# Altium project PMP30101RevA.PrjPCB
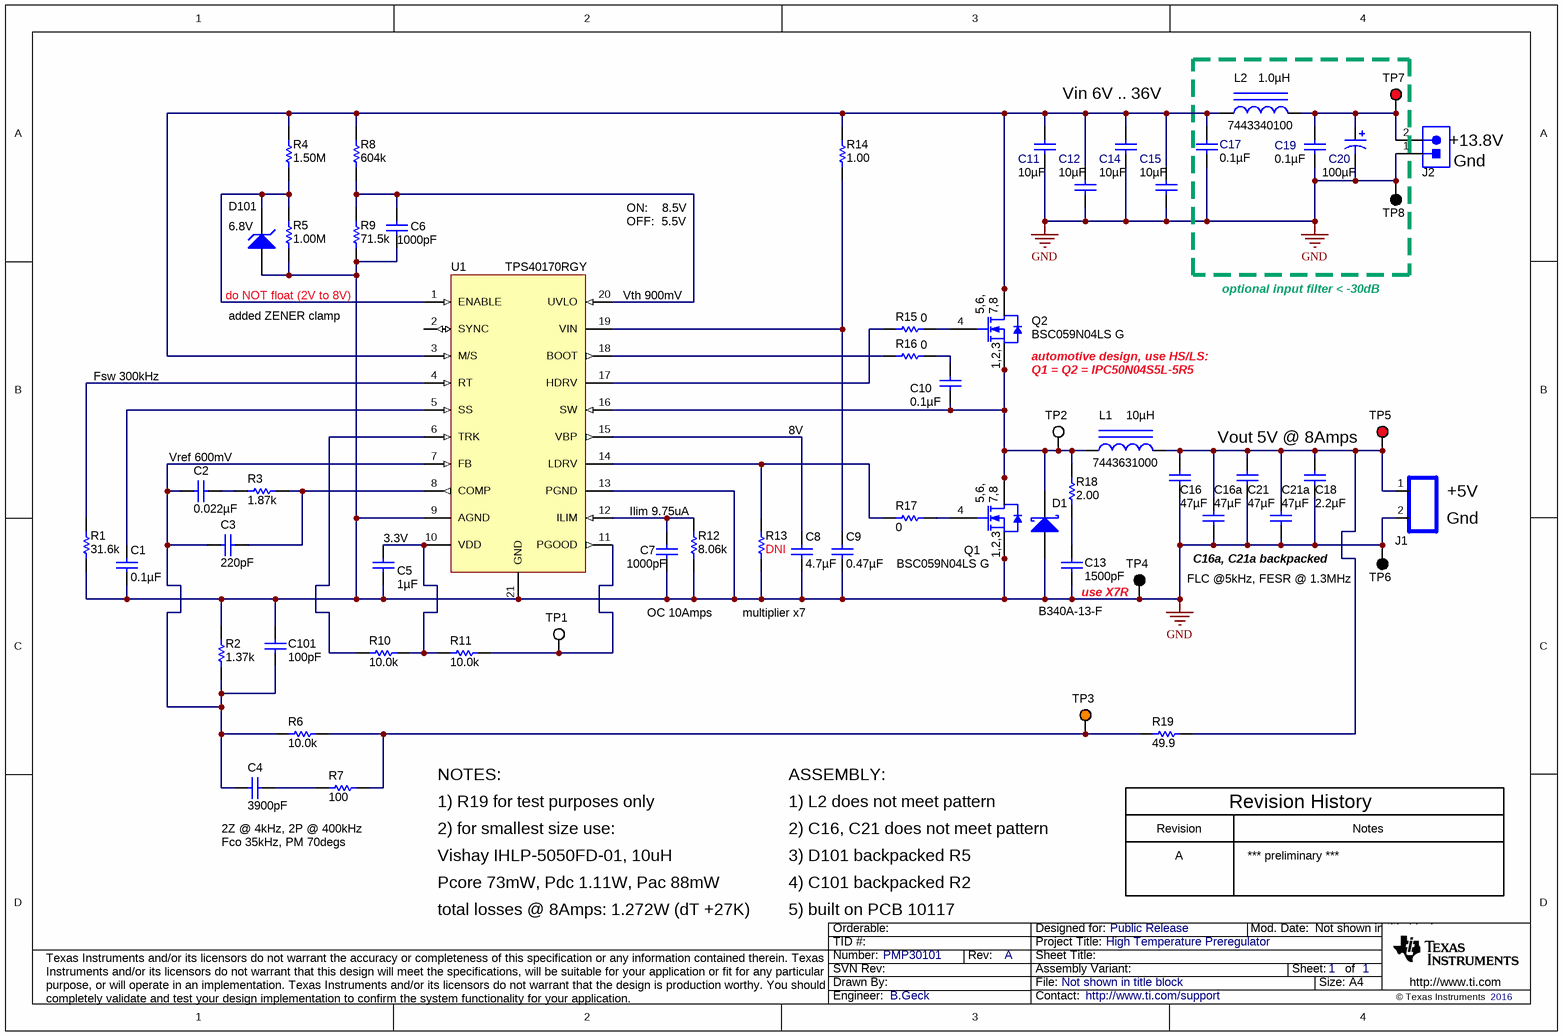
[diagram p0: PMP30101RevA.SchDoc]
CopyrightYear: 2016; PCB_Layout: B.Geck; PCB_Rev: A; PRJ_Customer: Public Release; PRJ_Engineer: B.Geck; PRJ_Number: PMP30101; PRJ_Title: High Temperature Preregulator; SCH_Rev: A; TechSupport: http://www.ti.com/support
1 sheet, 60 parts. Net scope: global (net labels, ports and power ports of the same name join across sheets).

## Sheet PMP30101RevA.SchDoc
size A4; Date: Not shown in title block; ApprovedBy: Not shown in title block; CheckedBy: Not shown in title block; Author: Not shown in title block; CompanyName: Not shown in title block; Engineer: Not shown in title block; Organization: Not shown in title block; Address1: Not shown in title block; Address2: Not shown in title block; Address3: Not shown in title block; Address4: Not shown in title block; DocumentNumber: 1; Revision: Use project parameter SCH_Rev; SheetNumber: 1; SheetTotal: 1; PageSetup: Record=PageOptions¦CenterHorizontal=True¦CenterVertical=True¦PrintScale=0.70¦XCorrection=1.00¦YCorrection=1.00¦PrintKind=0¦BorderSize=5000000¦LeftOffset=0¦BottomOffset=0¦Orientation=2¦PaperLength=1000¦PaperWidth=1000¦Scale=100¦PaperSource=15¦PrintQuality=600¦MediaType=1¦DitherType=10¦PaperKind=A4¦PrintScaleMode=1

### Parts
C1  ValueDisplayed: 0.1µF  [0402]  (hidden comment: GRM155R71C104KA88D)
C2  ValueDisplayed: 0.022µF  [0402]  (hidden comment: GRM155R71E223KA61D)
C3  ValueDisplayed: 220pF  [0402]  (hidden comment: GRM155R71H221KA01D)
C4  ValueDisplayed: 3900pF  [0402]  (hidden comment: GRM155R71H392KA01D)
C5  ValueDisplayed: 1µF  [0603]  (hidden comment: GRM188R71C105KA12D)
C6  ValueDisplayed: 1000pF  [0402]  (hidden comment: GRM155R71C102KA01D)
C7  ValueDisplayed: 1000pF  [0402]  (hidden comment: GRM155R71C102KA01D)
C8  ValueDisplayed: 4.7µF  [0805_HV]  (hidden comment: GRM21BR71C475KA73L)
C9  ValueDisplayed: 0.47µF  [0805_HV]  (hidden comment: GRM21BR72A474KA73L)
C10  ValueDisplayed: 0.1µF  [0603]  (hidden comment: GRM188R72A104KA35D)
C11  ValueDisplayed: 10µF  [1210_270]  (hidden comment: GRM32ER71H106KA12L)
C12  ValueDisplayed: 10µF  [1210_270]  (hidden comment: GRM32ER71H106KA12L)
C13  ValueDisplayed: 1500pF  [0603]  (hidden comment: GRM188R72A152KA01D)
C14  ValueDisplayed: 10µF  [1210_270]  (hidden comment: GRM32ER71H106KA12L)
C15  ValueDisplayed: 10µF  [1210_270]  (hidden comment: GRM32ER71H106KA12L)
C16  ValueDisplayed: 47µF  [1210_270]  (hidden comment: GRM32ER71A476KE15L)
C16a  ValueDisplayed: 47µF  [1210_270]  (hidden comment: GRM32ER71A476KE15L)
C17  ValueDisplayed: 0.1µF  [0603]  (hidden comment: GRM188R71H104KA93D)
C18  ValueDisplayed: 2.2µF  [0603]  (hidden comment: GRM188R71A225KE15D)
C19  ValueDisplayed: 0.1µF  [0603]  (hidden comment: GRM188R71H104KA93D)
C20  ValueDisplayed: 100µF  [SM_RADIAL_10BMM]  (hidden comment: EEHZC1H101P)
C21  ValueDisplayed: 47µF  [1210_270]  (hidden comment: GRM32ER71A476KE15L)
C21a  ValueDisplayed: 47µF  [1210_270]  (hidden comment: GRM32ER71A476KE15L)
C101  ValueDisplayed: 100pF  [0402]  (hidden comment: GRM1555C1H101JA01D)
D1  B340A-13-F  [SMA]
D101  value 6.8V  [SOD-323]  (hidden comment: MMSZ5235BS-7-F)
J1  TBLK_15A_2X5.1MM  [TB_2X5.1MM]  (value not drawn)
J2  ED555/2DS  [TERM_BLK_ED555-2DS]  (value not drawn)
L1  7443631000  ValueDisplayed: 10µH  [WE-HCF_2013]
L2  7443340100  ValueDisplayed: 1.0µH  [WE-HCC-8X7]
Q1  BSC059N04LS G  [PG-TDSON-8]
Q2  BSC059N04LS G  [PG-TDSON-8]
R1  ValueDisplayed: 31.6k  [0402]  (hidden comment: CRCW040231K6FKED)
R2  ValueDisplayed: 1.37k  [0402]  (hidden comment: CRCW04021K37FKED)
R3  ValueDisplayed: 1.87k  [0402]  (hidden comment: CRCW04021K87FKED)
R4  ValueDisplayed: 1.50M  [0603]  (hidden comment: CRCW06031M50FKEA)
R5  ValueDisplayed: 1.00M  [0402]  (hidden comment: CRCW04021M00FKED)
R6  ValueDisplayed: 10.0k  [0402]  (hidden comment: CRCW040210K0FKED)
R7  ValueDisplayed: 100  [0402]  (hidden comment: CRCW0402100RFKED)
R8  ValueDisplayed: 604k  [0603]  (hidden comment: CRCW0603604KFKEA)
R9  ValueDisplayed: 71.5k  [0402]  (hidden comment: CRCW040271K5FKED)
R10  ValueDisplayed: 10.0k  [0402]  (hidden comment: CRCW040210K0FKED)
R11  ValueDisplayed: 10.0k  [0402]  (hidden comment: CRCW040210K0FKED)
R12  ValueDisplayed: 8.06k  [0402]  (hidden comment: CRCW04028K06FKED)
R13  ValueDisplayed: DNI  [0402]  (hidden comment: CRCW040210K0FKED)
R14  ValueDisplayed: 1.00  [0603]  (hidden comment: CRCW06031R00FKEA)
R15  ValueDisplayed: 0  [0402]  (hidden comment: CRCW04020000Z0ED)
R16  ValueDisplayed: 0  [0402]  (hidden comment: CRCW04020000Z0ED)
R17  ValueDisplayed: 0  [0402]  (hidden comment: CRCW04020000Z0ED)
R18  ValueDisplayed: 2.00  [1210M]  (hidden comment: ERJ-14BQF2R0U)
R19  ValueDisplayed: 49.9  [0402]  (hidden comment: CRCW040249R9FKED)
TP1  5002  [Keystone5002]  (value not drawn)
TP2  5002  [Keystone5002]  (value not drawn)
TP3  5003  [Keystone5003]  (value not drawn)
TP4  5001  [Keystone5001]  (value not drawn)
TP5  5000  [Keystone5000]  (value not drawn)
TP6  5001  [Keystone5001]  (value not drawn)
TP7  5000  [Keystone5000]  (value not drawn)
TP8  5001  [Keystone5001]  (value not drawn)
U1  TPS40170RGY  [RGY0020A]

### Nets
GND: C1.2 C5.2 C6.2 C7.2 C8.2 C9.2 C11.2 C12.2 C13.2 C14.2 C15.2 C16.2 C16a.2 C17.2 C18.2 C19.2 C20.2(-) C21.2 C21a.2 C101.1 D1.2(A) D101.2(A) J1.2 J2.1 Q1.1(S) Q1.2(S) Q1.3(S) R1.1 R2.2 R5.1 R9.1 R12.1 R13.1 TP4.1 TP6.1 TP8.1 U1.9(AGND) U1.13(PGND) U1.21(GND)
NetC1_1: C1.1 U1.5(SS)
NetC2_1: C2.1 R3.1
NetC2_2: C2.2 C3.2 C4.2 C101.2 R2.1 R6.2 U1.7(FB)
NetC3_1: C3.1 R3.2 U1.8(COMP)
NetC4_1: C4.1 R7.1
NetC5_1: C5.1 R10.1 R11.2 U1.10(VDD)
NetC6_1: C6.1 R8.1 R9.2 U1.20(UVLO)
NetC7_1: C7.1 R12.2 U1.12(ILIM)
NetC8_1: C8.1 U1.15(VBP)
NetC9_1: C9.1 R14.1 U1.19(VIN)
NetC10_1: C10.1 R16.2
NetC10_2: C10.2 D1.1(K) L1.1 Q1.5(D) Q1.6(D) Q1.7(D) Q1.8(D) Q1.9(D) Q2.1(S) Q2.2(S) Q2.3(S) R18.2 TP2.1 U1.16(SW)
NetC11_1: C11.1 C12.1 C14.1 C15.1 C17.1 L2.1 Q2.5(D) Q2.6(D) Q2.7(D) Q2.8(D) Q2.9(D) R4.2 R8.2 R14.2 U1.3(M/S)
NetC13_1: C13.1 R18.1
NetC16_1: C16.1 C16a.1 C18.1 C21.1 C21a.1 J1.1 L1.2 R19.2 TP5.1
NetC19_1: C19.1 C20.1(+) J2.2 L2.2 TP7.1
NetD101_1: D101.1(K) R4.1 R5.2 U1.1(ENABLE)
NetQ1_4: Q1.4(G) R17.2
NetQ2_4: Q2.4(G) R15.2
NetR1_2: R1.2 U1.4(RT)
NetR6_1: R6.1 R7.2 R19.1 TP3.1
NetR10_2: R10.2 U1.6(TRK)
NetR11_1: R11.1 TP1.1 U1.11(PGOOD)
NetR13_2: R13.2 R17.1 U1.14(LDRV)
NetR15_1: R15.1 U1.17(HDRV)
NetR16_1: R16.1 U1.18(BOOT)

Not connected (* = marked no-connect by the designer): U1 2(SYNC)

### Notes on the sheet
- Vin 6V .. 36V
- (near J2) Gnd
- (near J2) +13.8V
- ON:    8.5V
- OFF:  5.5V
- added ZENER clamp
- do NOT float (2V to 8V)
- (near U1) Vth 900mV
- optional input filter < -30dB
- Fsw 300kHz
- (near Q2) automotive design, use HS/LS:
- (near Q2) Q1 = Q2 = IPC50N04S5L-5R5
- 8V
- Vout 5V @ 8Amps
- Vref 600mV
- (near R12) Ilim 9.75uA
- (near J1) +5V
- (near J1) Gnd
- (near C5) 3.3V
- FLC @5kHz, FESR @ 1.3MHz
- C16a, C21a backpacked
- OC 10Amps
- multiplier x7
- use X7R
- NOTES:
- ASSEMBLY:
- 2Z @ 4kHz, 2P @ 400kHz
- Fco 35kHz, PM 70degs
- 1) R19 for test purposes only
- 2) for smallest size use:
- Vishay IHLP-5050FD-01, 10uH
- 1) L2 does not meet pattern
- 2) C16, C21 does not meet pattern
- 3) D101 backpacked R5
- Revision
- A
- *** preliminary ***
- Revision History
- Notes
- Pcore 73mW, Pdc 1.11W, Pac 88mW
- total losses @ 8Amps: 1.272W (dT +27K)
- 5) built on PCB 10117
- 4) C101 backpacked R2

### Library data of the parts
C1 = GRM155R71C104KA88D: CAP, CERM, 0.1 µF, 16 V, +/- 10%, X7R, 0402; Manufacturer: MuRata; Polarized: N; CompType: Capacitor; Value: 0.1uF; U/M: EA; Cap_F: 0.0000001; Tolerance_%: 10; Value1: Unknown; VDC_V: 16; Value2: 16V; TaMin_C: -55; TaMax_C: 125
C2 = GRM155R71E223KA61D: CAP, CERM, 0.022 µF, 25 V, +/- 10%, X7R, 0402; Manufacturer: MuRata; Polarized: N; CompType: Capacitor; Value: 0.022uF; U/M: EA; Cap_F: 0.000000022; Tolerance_%: 10; Value1: Unknown; VDC_V: 25; Value2: 25V; TaMin_C: -55; TaMax_C: 125; SizeArea_mm2: 0.5; SizeAreaWB_mm2: 3; SizeX_mm: 1; SizeZ_mm: 0.6; AEC Category: Q200
C3 = GRM155R71H221KA01D: CAP, CERM, 220 pF, 50 V, +/- 10%, X7R, 0402; Manufacturer: MuRata; Polarized: N; CompType: Capacitor; Value: 220pF; U/M: EA; Cap_F: 0.00000000022; Tolerance_%: 10; Value1: Unknown; VDC_V: 50; Value2: 50V; TaMin_C: -55; TaMax_C: 125; SizeArea_mm2: 0.5; SizeAreaWB_mm2: 3; SizeX_mm: 1; SizeZ_mm: 0.6; AEC Category: Q200
C4 = GRM155R71H392KA01D: CAP, CERM, 3900 pF, 50 V, +/- 10%, X7R, 0402; Manufacturer: MuRata; Polarized: N; CompType: Capacitor; Value: 3900pF; U/M: EA; Cap_F: 0.0000000039; Tolerance_%: 10; Value1: Unknown; VDC_V: 50; Value2: 50V; TaMin_C: -55; TaMax_C: 125; SizeArea_mm2: 0.5; SizeAreaWB_mm2: 3; SizeX_mm: 1; SizeZ_mm: 0.6; AEC Category: Q200
C5 = GRM188R71C105KA12D: CAP, CERM, 1 µF, 16 V, +/- 10%, X7R, 0603; Manufacturer: MuRata; Polarized: N; CompType: Capacitor; Value: 1uF; U/M: EA; Cap_F: 0.000001; Tolerance_%: 10; ESR_ohm: 0.011; Value1: 0.011 ohm; VDC_V: 16; Value2: 16V; TaMin_C: -55; TaMax_C: 125
C6 C7 = GRM155R71C102KA01D: CAP, CERM, 1000 pF, 16 V, +/- 10%, X7R, 0402; Manufacturer: MuRata; Polarized: N; CompType: Capacitor; Value: 1000pF; U/M: EA; Cap_F: 0.000000001; Tolerance_%: 10; Value1: Unknown; VDC_V: 16; Value2: 16V; TaMin_C: -55; TaMax_C: 125
C8 = GRM21BR71C475KA73L: CAP, CERM, 4.7 µF, 16 V, +/- 10%, X7R, 0805; Manufacturer: MuRata; Polarized: N; CompType: Capacitor; Value: 4.7uF; U/M: EA; Cap_F: 0.0000047; Tolerance_%: 10; ESR_ohm: 0.006; Value1: 0.006 ohm; VDC_V: 16; Value2: 16V; TaMin_C: -55; TaMax_C: 125; Cap_Case: 0805
C9 = GRM21BR72A474KA73L: CAP, CERM, 0.47 µF, 100 V, +/- 10%, X7R, 0805; Manufacturer: MuRata; Polarized: N; CompType: Capacitor; Value: 0.47uF; U/M: EA; Cap_F: 0.00000047; Tolerance_%: 10; Value1: Unknown; VDC_V: 100; Value2: 100V; TaMin_C: -55; TaMax_C: 125; Cap_Case: 0805
C10 = GRM188R72A104KA35D: CAP, CERM, 0.1 µF, 100 V, +/- 10%, X7R, 0603; Manufacturer: MuRata; Polarized: N; CompType: Capacitor; Value: 0.1uF; U/M: EA; Cap_F: 0.0000001; Tolerance_%: 10; Value1: Unknown; VDC_V: 100; Value2: 100V; TaMin_C: -55; TaMax_C: 125
C11 C12 C14 C15 = GRM32ER71H106KA12L: CAP, CERM, 10 µF, 50 V, +/- 10%, X7R, 1210; Manufacturer: MuRata; Polarized: N; CompType: Capacitor; Value: 10uF; U/M: EA; Cap_F: 0.00001; Tolerance_%: 10; Value1: Unknown; VDC_V: 50; Value2: 50V; TaMin_C: -55; TaMax_C: 125; Cap_Case: 1210; SizeArea_mm2: 8; SizeAreaWB_mm2: 14.7; SizeX_mm: 3.2; SizeY_mm: 2.5; SizeZ_mm: 2.7; AEC Category: Q200
C13 = GRM188R72A152KA01D: CAP, CERM, 1500 pF, 100 V, +/- 10%, X7R, 0603; Manufacturer: MuRata; Polarized: N; CompType: Capacitor; Value: 1500pF; U/M: EA; Cap_F: 0.0000000015; Tolerance_%: 10; Value1: Unknown; VDC_V: 100; Value2: 100V; TaMin_C: -55; TaMax_C: 125; SizeArea_mm2: 1.28; SizeAreaWB_mm2: 4.68; SizeX_mm: 1.6; SizeY_mm: 0.8; SizeZ_mm: 1; AEC Category: Q200
C16 C16a C21 C21a = GRM32ER71A476KE15L: CAP, CERM, 47 µF, 10 V, +/- 10%, X7R, 1210; Manufacturer: MuRata; Polarized: N; CompType: Capacitor; Value: 47uF; U/M: EA; Cap_F: 0.000047; Tolerance_%: 10; Value1: Unknown; Value2: 10V; TaMin_C: -55; TaMax_C: 125; Cap_Case: 1210; SizeArea_mm2: 8; SizeAreaWB_mm2: 14.7; SizeX_mm: 3.2; SizeY_mm: 2.5; SizeZ_mm: 2.7; AEC Category: Q200
C17 C19 = GRM188R71H104KA93D: CAP, CERM, 0.1 µF, 50 V, +/- 10%, X7R, 0603; Manufacturer: MuRata; Polarized: N; CompType: Capacitor; Value: 0.1uF; U/M: EA; Cap_F: 0.0000001; Tolerance_%: 10; Value1: Unknown; VDC_V: 50; Value2: 50V; TaMin_C: -55; TaMax_C: 125; SizeArea_mm2: 1.28; SizeAreaWB_mm2: 4.68; SizeX_mm: 1.6; SizeY_mm: 0.8; SizeZ_mm: 1; AEC Category: Q200
C18 = GRM188R71A225KE15D: CAP, CERM, 2.2 µF, 10 V, +/- 10%, X7R, 0603; Manufacturer: MuRata; Polarized: N; CompType: Capacitor; Value: 2.2uF; U/M: EA; Cap_F: 0.0000022; Tolerance_%: 10; ESR_ohm: 0.009; Value1: 0.009 ohm; Value2: 10V; TaMin_C: -55; TaMax_C: 125
C20 = EEHZC1H101P: CAP, Polymer Hybrid, 100 µF, 50 V, +/- 20%, 28 ohm, 10x10 SMD; Manufacturer: Panasonic; Polarized: Y; CompType: Capacitor; Value: 100uF; U/M: EA; Cap_F: 0.0001; Tolerance_%: 20; Value1: 28 ohm; VDC_V: 50; Value2: 50V; ESR_ohm: 28; IRMS_A: 1.6; TaMin_C: -55; TaMax_C: 125; AEC Category: Q200
C101 = GRM1555C1H101JA01D: CAP, CERM, 100 pF, 50 V, +/- 5%, C0G/NP0, 0402; Manufacturer: MuRata; Polarized: N; CompType: Capacitor; Value: 100pF; U/M: EA; Cap_F: 0.0000000001; Tolerance_%: 5; Value1: Unknown; VDC_V: 50; Value2: 50V; TaMin_C: -55; TaMax_C: 125; SizeArea_mm2: 0.5; SizeAreaWB_mm2: 3; SizeX_mm: 1; SizeZ_mm: 0.6; AEC Category: Q200
D1 = B340A-13-F: Diode, Schottky, 40 V, 3 A, SMA; Manufacturer: Diodes Inc.; U/M: EA; Vf_V: 0.5; Value: 40V; Value1: 3A; Value2: 0.5V; Io_A: 3; Vr_V: 40; TJmax_C: 125; RJC_CperW: 25; SizeAreaWB_mm2: 37.3428; SizeArea_mm2: 16.3228; SizeX_mm: 5.59; SizeY_mm: 2.92; SizeZ_mm: 2.87; AEC Category: Q101
D101 = MMSZ5235BS-7-F: Diode, Zener, 6.8 V, 200 mW, SOD-323; Manufacturer: Diodes Inc.; SymbolCreator: a0412235; U/M: EA; Power_W: 0.2; Vz_V: 6.8; Value1: 0.2W; RJA_CperW: 350; SizeAreaWB_mm2: 8.695; SizeArea_mm2: 3.645; SizeX_mm: 2.7; SizeY_mm: 1.35; SizeZ_mm: 1; AEC Category: Q101
J1 = TBLK_15A_2X5.1MM: Terminal Block, 2-pin, 15-A, 5.1mm; Manufacturer: OST; PartNumber: ED120/2DS; area: 141600; Value: ED120/2DS
J2 = ED555/2DS: Terminal Block, 6A, 3.5mm Pitch, 2-Pos, TH; Manufacturer: On-Shore Technology; SymbolCreator: a0412235; CompType: Connector; U/M: EA
L1 = 7443631000: Inductor, Shielded Drum Core, Mn-Zn, 10 µH, 16 A, 0.00796 ohm, SMD; Manufacturer: Wurth Elektronik; Value: 10uH; Ind_H: 10.0E-6; Imax_A: 16; Irms: 16A @ 50C rise; Isat: 23A @ 30% inductance drop; Value2: 16A; AEC Category: Q200
L2 = 7443340150: Inductor, Shielded Drum Core, Ferrite, 1.0 µH, 17 A, 0.0036 ohm, SMD; Manufacturer: Wurth Elektronik eiSos; Value: 1.0uH; Ind_H: 1.0E-6; Imax_A: 17; Irms: 17A @ 50C rise; Isat: 24A @ 30% inductance drop; DCR_ohm: 0.0036; Value2: 17A
Q1 Q2 = BSC059N04LS G: MOSFET, N-CH, 40 V, 73 A, PG-TDSON-8; Manufacturer: Infineon Technologies; Alternate Manufacturer: None; U/M: EA; ChType: N; Value: 40V; VdsMax_V: 40; Value1: 0.0085 ohm; Rdson45_ohm: 0.0085; Value2: 30 nC; QgTyp_nC: 30; Vgs_V: 20; IdsMax_A: 73; SizeAreaWB_mm2: 55.131; SizeArea_mm2: 29.351; SizeX_mm: 5.99; SizeY_mm: 4.9; SizeZ_mm: 1.12; AEC Category: Q101
R1 = CRCW040231K6FKED: RES, 31.6 k, 1%, 0.063 W, 0402; Manufacturer: Vishay-Dale; CompType: Resistor; Value: 31.6k; Res_ohm: 31600; Value_Code: 31k6; Tolerance_%: 1; Power_W: 0.063; Value2: 0.063W; VDC_V: 50; TempCo: 100 ppm/C; SizeArea_mm2: 0.5; SizeZ_mm: 0.6; EIA_Code: E96; U/M: EA; AEC Category: Q200
R2 = CRCW04021K37FKED: RES, 1.37 k, 1%, 0.063 W, 0402; Manufacturer: Vishay-Dale; CompType: Resistor; Value: 1.37k; Res_ohm: 1370; Value_Code: 1k37; Tolerance_%: 1; Power_W: 0.063; Value2: 0.063W; VDC_V: 50; TempCo: 100 ppm/C; SizeArea_mm2: 0.5; SizeZ_mm: 0.6; EIA_Code: E96; U/M: EA; AEC Category: Q200
R3 = CRCW04021K87FKED: RES, 1.87 k, 1%, 0.063 W, 0402; Manufacturer: Vishay-Dale; CompType: Resistor; Value: 1.87k; Res_ohm: 1870; Value_Code: 1k87; Tolerance_%: 1; Power_W: 0.063; Value2: 0.063W; VDC_V: 50; TempCo: 100 ppm/C; SizeArea_mm2: 0.5; SizeZ_mm: 0.6; EIA_Code: E96; U/M: EA; AEC Category: Q200
R4 = CRCW06031M50FKEA: RES, 1.50 M, 1%, 0.1 W, 0603; Manufacturer: Vishay-Dale; CompType: Resistor; Value: 1.50Meg; Res_ohm: 1500000; Value_Code: 1M50; Tolerance_%: 1; Power_W: 0.1; Value2: 0.1W; VDC_V: 75; TempCo: 100 ppm/C; SizeArea_mm2: 1.28; SizeX_mm: 1.6; SizeY_mm: 0.8; EIA_Code: E96; U/M: EA; AEC Category: Q200
R5 = CRCW04021M00FKED: RES, 1.00 M, 1%, 0.063 W, 0402; Manufacturer: Vishay-Dale; CompType: Resistor; Value: 1.00Meg; Res_ohm: 1000000; Value_Code: 1M00; Tolerance_%: 1; Power_W: 0.063; Value2: 0.063W; VDC_V: 50; TempCo: 100 ppm/C; SizeArea_mm2: 0.5; SizeZ_mm: 0.6; EIA_Code: E96; U/M: EA; AEC Category: Q200
R6 R10 R11 R13 = CRCW040210K0FKED: RES, 10.0 k, 1%, 0.063 W, 0402; Manufacturer: Vishay-Dale; CompType: Resistor; Res_ohm: 10000; Value: 10.0k; Value_Code: 10k0; Tolerance_%: 1; Power_W: 0.063; Value2: 0.063W; VDC_V: 50; TempCo: 100 ppm/C; EIA_Code: E96; U/M: EA
R7 = CRCW0402100RFKED: RES, 100, 1%, 0.063 W, 0402; Manufacturer: Vishay-Dale; CompType: Resistor; Value: 100; Value_Code: 100R; Tolerance_%: 1; Power_W: 0.063; Value2: 0.063W; VDC_V: 50; TempCo: 100 ppm/C; SizeArea_mm2: 0.5; SizeZ_mm: 0.6; EIA_Code: E96; U/M: EA; AEC Category: Q200
R8 = CRCW0603604KFKEA: RES, 604 k, 1%, 0.1 W, 0603; Manufacturer: Vishay-Dale; CompType: Resistor; Value: 604k; Res_ohm: 604000; Tolerance_%: 1; Power_W: 0.1; Value2: 0.1W; VDC_V: 75; TempCo: 100 ppm/C; SizeArea_mm2: 1.28; SizeX_mm: 1.6; SizeY_mm: 0.8; EIA_Code: E96; U/M: EA; AEC Category: Q200
R9 = CRCW040271K5FKED: RES, 71.5 k, 1%, 0.063 W, 0402; Manufacturer: Vishay-Dale; CompType: Resistor; Value: 71.5k; Res_ohm: 71500; Value_Code: 71k5; Tolerance_%: 1; Power_W: 0.063; Value2: 0.063W; VDC_V: 50; TempCo: 100 ppm/C; SizeArea_mm2: 0.5; SizeZ_mm: 0.6; EIA_Code: E96; U/M: EA; AEC Category: Q200
R12 = CRCW04028K06FKED: RES, 8.06 k, 1%, 0.063 W, 0402; Manufacturer: Vishay-Dale; CompType: Resistor; Value: 8.06k; Res_ohm: 8060; Value_Code: 8k06; Tolerance_%: 1; Power_W: 0.063; Value2: 0.063W; VDC_V: 50; TempCo: 100 ppm/C; SizeArea_mm2: 0.5; SizeZ_mm: 0.6; EIA_Code: E96; U/M: EA; AEC Category: Q200
R14 = CRCW06031R00FKEA: RES, 1.00, 1%, 0.1 W, 0603; Manufacturer: Vishay-Dale; CompType: Resistor; Value: 1.00; Res_ohm: 1; Value_Code: 1R00; Power_W: 0.1; Value2: 0.1W; VDC_V: 75; TempCo: 100 ppm/C; EIA_Code: E96; U/M: EA
R15-R17 = CRCW04020000Z0ED: RES, 0, 5%, 0.063 W, 0402; Manufacturer: Vishay-Dale; CompType: Resistor; Value: 0; Value_Code: 0000; Tolerance_%: 5; Power_W: 0.063; Value2: 0.063W; VDC_V: 50; TempCo: 200 ppm/C; EIA_Code: E24; U/M: EA
R18 = ERJ-14BQF2R0U: RES, 2.00, 1%, 0.5 W, AEC-Q200 Grade 0, 1210; Manufacturer: Panasonic; CompType: Resistor; Value: 2.00; Res_ohm: 2; Value_Code: 2R00; Tolerance_%: 1; Power_W: 0.5; Value2: 0.5W; TempCo: 100 ppm/C; SizeArea_mm2: 8; SizeAreaWB_mm2: 14.7; SizeX_mm: 3.2; SizeY_mm: 2.5; SizeZ_mm: 1.35; EIA_Code: E96; U/M: EA; AEC Category: Q200; AEC Qualified: Y; AEC Grade: 0
R19 = CRCW040249R9FKED: RES, 49.9, 1%, 0.063 W, 0402; Manufacturer: Vishay-Dale; CompType: Resistor; Value: 49.9; Value_Code: 49R9; Tolerance_%: 1; Power_W: 0.063; Value2: 0.063W; VDC_V: 50; TempCo: 100 ppm/C; EIA_Code: E96; U/M: EA
TP1 TP2 = 5002: Test Point, Miniature, White, TH; Manufacturer: Keystone; CompType: Test Point Loop; U/M: EA
TP3 = 5003: Test Point, Miniature, Orange, TH; Manufacturer: Keystone; CompType: Test Point Loop; U/M: EA
TP4 TP6 TP8 = 5001: Test Point, Miniature, Black, TH; Manufacturer: Keystone; CompType: Test Point Loop; U/M: EA
TP5 TP7 = 5000: Test Point, Miniature, Red, TH; Manufacturer: Keystone; CompType: Test Point Loop; U/M: EA
U1 = TPS40170RGY: 4.5-v to 60-v wide-input synchronous PWM buck controller, RGY0020A; Alternate Manufacturer: None; Manufacturer: Texas Instruments; SymbolCreator: a0412235/PADS; CompType: IC; U/M: EA

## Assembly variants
001: all parts fitted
